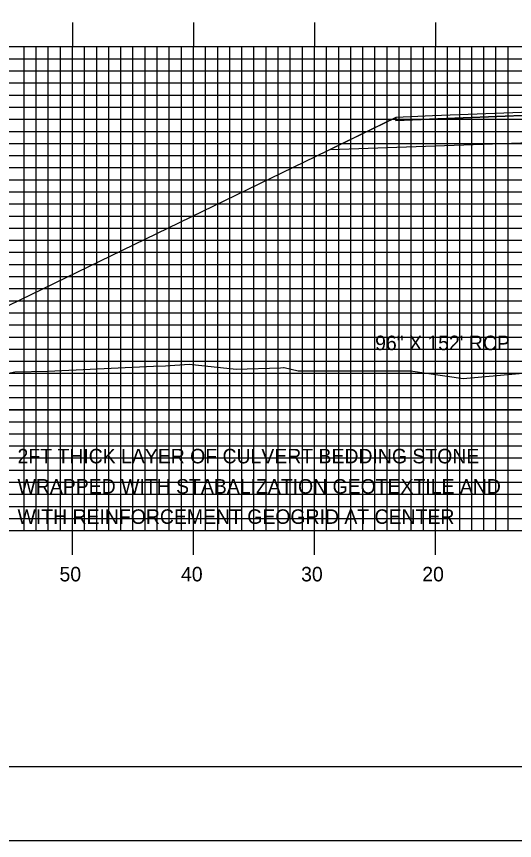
# Model space of a CAD drawing. Extents: x 1758647 to 1758990, y 442323 to 442543.
# Drawn here: x 1758757.8 to 1758799, y 442323.3 to 442391.4 of the extents above; entities that cross this region are included whole.
import ezdxf

# ---------------------------------------------------------------- set-up
doc = ezdxf.new("R2010")
doc.units = 0
for name, color, linetype in [('BORDER', 7, 'Continuous'), ('D_Drainage_Culvert', 7, 'Continuous'), ('D_Drainage_Text', 7, 'Continuous'), ('D_Roadway_Edge_Shoulder', 7, 'Continuous'), ('D_Roadway_FinishedGrade', 7, 'Continuous'), ('D_Roadway_SubGrade', 7, 'Continuous'), ('D_Text_Standard', 7, 'Continuous'), ('H_V ANNOTATION', 7, 'Continuous'), ('MAJOR', 7, 'Continuous'), ('MINOR', 7, 'Continuous'), ('PLOT BOUNDARY', 7, 'Continuous'), ('S_Roadway_Centerline', 7, 'Continuous')]:
    doc.layers.add(name, color=color, linetype=linetype)

msp = doc.modelspace()

# ---------------------------------------------------------------- linework, layer by layer
at = {"layer": 'BORDER'}
msp.add_lwpolyline([(1758662.822, 442329.386), (1758982.822, 442329.386), (1758982.822, 442539.386), (1758662.822, 442539.386)], close=True, dxfattribs=at)
at = {"layer": 'D_Drainage_Culvert'}
for p, q in [((1758743.557, 442358.886), (1758895.557, 442358.886)), ((1758745.057, 442358.879), (1758894.057, 442358.879)), ((1758745.057, 442357.886), (1758894.057, 442357.886)), ((1758745.057, 442356.886), (1758894.057, 442356.886))]:
    msp.add_line(p, q, dxfattribs=at)
msp.add_lwpolyline([(1758743.557, 442366.886), (1758895.557, 442366.886), (1758895.557, 442358.886)], dxfattribs=at)
at = {"layer": 'D_Roadway_Edge_Shoulder'}
msp.add_lwpolyline([(1758800.273, 442383.461), (1758792.173, 442383.154), (1758792.173, 442383.154), (1758789.135, 442383.038), (1758789.135, 442382.788), (1758800.273, 442383.211)], close=True, dxfattribs=at)
at = {"layer": 'D_Roadway_FinishedGrade'}
for p, q in [((1758743.557, 442360.886), (1758789.135, 442383.038)), ((1758789.135, 442383.038), (1758787.135, 442382.038)), ((1758733.557, 442360.886), (1758905.557, 442360.886))]:
    msp.add_line(p, q, dxfattribs=at)
at = {"layer": 'D_Roadway_SubGrade'}
msp.add_lwpolyline([(1758800.273, 442382.794), (1758800.273, 442383.211), (1758789.135, 442382.788), (1758789.135, 442383.038), (1758783.715, 442380.398), (1758800.273, 442380.961)], close=True, dxfattribs=at)
at = {"layer": 'MAJOR'}
for p, q in [((1758762.422, 442390.89), (1758762.422, 442388.886)), ((1758772.422, 442390.89), (1758772.422, 442388.886)), ((1758782.422, 442390.89), (1758782.422, 442388.886)), ((1758792.422, 442390.89), (1758792.422, 442388.886)), ((1758672.422, 442388.886), (1758952.422, 442388.886)), ((1758672.422, 442388.886), (1758952.422, 442388.886)), ((1758762.422, 442348.886), (1758762.422, 442388.886)), ((1758772.422, 442348.886), (1758772.422, 442388.886)), ((1758782.422, 442348.886), (1758782.422, 442388.886)), ((1758792.422, 442348.886), (1758792.422, 442388.886)), ((1758672.422, 442383.886), (1758952.422, 442383.886)), ((1758672.422, 442378.886), (1758952.422, 442378.886)), ((1758672.422, 442373.886), (1758952.422, 442373.886)), ((1758672.422, 442368.886), (1758952.422, 442368.886)), ((1758672.422, 442363.886), (1758952.422, 442363.886)), ((1758672.422, 442358.886), (1758952.422, 442358.886)), ((1758672.422, 442353.886), (1758952.422, 442353.886)), ((1758672.422, 442348.886), (1758952.422, 442348.886)), ((1758672.422, 442348.886), (1758952.422, 442348.886)), ((1758762.422, 442346.882), (1758762.422, 442348.886)), ((1758772.422, 442346.882), (1758772.422, 442348.886)), ((1758782.422, 442346.882), (1758782.422, 442348.886)), ((1758792.422, 442346.882), (1758792.422, 442348.886))]:
    msp.add_line(p, q, dxfattribs=at)
at = {"layer": 'MINOR'}
for p, q in [((1758758.422, 442348.886), (1758758.422, 442388.886)), ((1758759.422, 442348.886), (1758759.422, 442388.886)), ((1758760.422, 442348.886), (1758760.422, 442388.886)), ((1758761.422, 442348.886), (1758761.422, 442388.886)), ((1758763.422, 442348.886), (1758763.422, 442388.886)), ((1758764.422, 442348.886), (1758764.422, 442388.886)), ((1758765.422, 442348.886), (1758765.422, 442388.886)), ((1758766.422, 442348.886), (1758766.422, 442388.886)), ((1758767.422, 442348.886), (1758767.422, 442388.886)), ((1758768.422, 442348.886), (1758768.422, 442388.886)), ((1758769.422, 442348.886), (1758769.422, 442388.886)), ((1758770.422, 442348.886), (1758770.422, 442388.886)), ((1758771.422, 442348.886), (1758771.422, 442388.886)), ((1758773.422, 442348.886), (1758773.422, 442388.886)), ((1758774.422, 442348.886), (1758774.422, 442388.886)), ((1758775.422, 442348.886), (1758775.422, 442388.886)), ((1758776.422, 442348.886), (1758776.422, 442388.886)), ((1758777.422, 442348.886), (1758777.422, 442388.886)), ((1758778.422, 442348.886), (1758778.422, 442388.886)), ((1758779.422, 442348.886), (1758779.422, 442388.886)), ((1758780.422, 442348.886), (1758780.422, 442388.886)), ((1758781.422, 442348.886), (1758781.422, 442388.886)), ((1758783.422, 442348.886), (1758783.422, 442388.886)), ((1758784.422, 442348.886), (1758784.422, 442388.886)), ((1758785.422, 442348.886), (1758785.422, 442388.886)), ((1758786.422, 442348.886), (1758786.422, 442388.886)), ((1758787.422, 442348.886), (1758787.422, 442388.886)), ((1758788.422, 442348.886), (1758788.422, 442388.886)), ((1758789.422, 442348.886), (1758789.422, 442388.886)), ((1758790.422, 442348.886), (1758790.422, 442388.886)), ((1758791.422, 442348.886), (1758791.422, 442388.886)), ((1758793.422, 442348.886), (1758793.422, 442388.886)), ((1758794.422, 442348.886), (1758794.422, 442388.886)), ((1758795.422, 442348.886), (1758795.422, 442388.886)), ((1758796.422, 442348.886), (1758796.422, 442388.886)), ((1758797.422, 442348.886), (1758797.422, 442388.886)), ((1758798.422, 442348.886), (1758798.422, 442388.886)), ((1758672.422, 442387.886), (1758952.422, 442387.886)), ((1758672.422, 442386.886), (1758952.422, 442386.886)), ((1758672.422, 442385.886), (1758952.422, 442385.886)), ((1758672.422, 442384.886), (1758952.422, 442384.886)), ((1758672.422, 442382.886), (1758952.422, 442382.886)), ((1758672.422, 442381.886), (1758952.422, 442381.886)), ((1758672.422, 442380.886), (1758952.422, 442380.886)), ((1758672.422, 442379.886), (1758952.422, 442379.886)), ((1758672.422, 442377.886), (1758952.422, 442377.886)), ((1758672.422, 442376.886), (1758952.422, 442376.886)), ((1758672.422, 442375.886), (1758952.422, 442375.886)), ((1758672.422, 442374.886), (1758952.422, 442374.886)), ((1758672.422, 442372.886), (1758952.422, 442372.886)), ((1758672.422, 442371.886), (1758952.422, 442371.886)), ((1758672.422, 442370.886), (1758952.422, 442370.886)), ((1758672.422, 442369.886), (1758952.422, 442369.886)), ((1758672.422, 442367.886), (1758952.422, 442367.886)), ((1758672.422, 442366.886), (1758952.422, 442366.886)), ((1758672.422, 442365.886), (1758952.422, 442365.886)), ((1758672.422, 442364.886), (1758952.422, 442364.886)), ((1758672.422, 442362.886), (1758952.422, 442362.886)), ((1758672.422, 442361.886), (1758952.422, 442361.886)), ((1758672.422, 442360.886), (1758952.422, 442360.886)), ((1758672.422, 442359.886), (1758952.422, 442359.886)), ((1758672.422, 442357.886), (1758952.422, 442357.886)), ((1758672.422, 442356.886), (1758952.422, 442356.886)), ((1758672.422, 442355.886), (1758952.422, 442355.886)), ((1758672.422, 442354.886), (1758952.422, 442354.886)), ((1758672.422, 442352.886), (1758952.422, 442352.886)), ((1758672.422, 442351.886), (1758952.422, 442351.886)), ((1758672.422, 442350.886), (1758952.422, 442350.886)), ((1758672.422, 442349.886), (1758952.422, 442349.886))]:
    msp.add_line(p, q, dxfattribs=at)
at = {"layer": 'PLOT BOUNDARY'}
msp.add_lwpolyline([(1758646.635, 442323.268), (1758986.635, 442323.268), (1758986.635, 442543.268), (1758646.635, 442543.268)], close=True, dxfattribs=at)
at = {"layer": 'S_Roadway_Centerline'}
msp.add_lwpolyline([(1758720.616, 442361.935), (1758728.029, 442361.909), (1758733.603, 442361.768), (1758739.117, 442361.502), (1758746.899, 442361.242), (1758747.935, 442361.142), (1758752.489, 442361.14), (1758754.206, 442361.463), (1758755.963, 442361.637), (1758757.654, 442362.01), (1758760.386, 442362.066), (1758769.125, 442362.474), (1758770.123, 442362.511), (1758772.073, 442362.642), (1758775.96, 442362.222), (1758779.604, 442362.343), (1758779.872, 442362.377), (1758779.885, 442362.371), (1758779.928, 442362.359), (1758781.08, 442362.092), (1758790.345, 442362.089), (1758794.711, 442361.446), (1758800.878, 442362.014)], dxfattribs=at)

# ---------------------------------------------------------------- texts
at = {"layer": 'D_Drainage_Text'}
msp.add_text('96" X 152\' RCP', height=1.2, dxfattribs=at).set_placement((1758787.436, 442363.799))
at = {"layer": 'D_Text_Standard'}
for s, p in [('2FT THICK LAYER OF CULVERT BEDDING STONE', (1758757.882, 442354.441)), ('WRAPPED WITH STABALIZATION GEOTEXTILE AND', (1758757.882, 442351.941)), ('WITH REINFORCEMENT GEOGRID AT CENTER', (1758757.882, 442349.441))]:
    msp.add_text(s, height=1.2, dxfattribs=at).set_placement(p)
at = {"layer": 'H_V ANNOTATION'}
for s, p in [('50', (1758761.351, 442344.686)), ('40', (1758771.394, 442344.686)), ('30', (1758781.319, 442344.686)), ('20', (1758791.33, 442344.686))]:
    msp.add_text(s, height=1.2, dxfattribs=at).set_placement(p)

doc.saveas('drawing.dxf')
